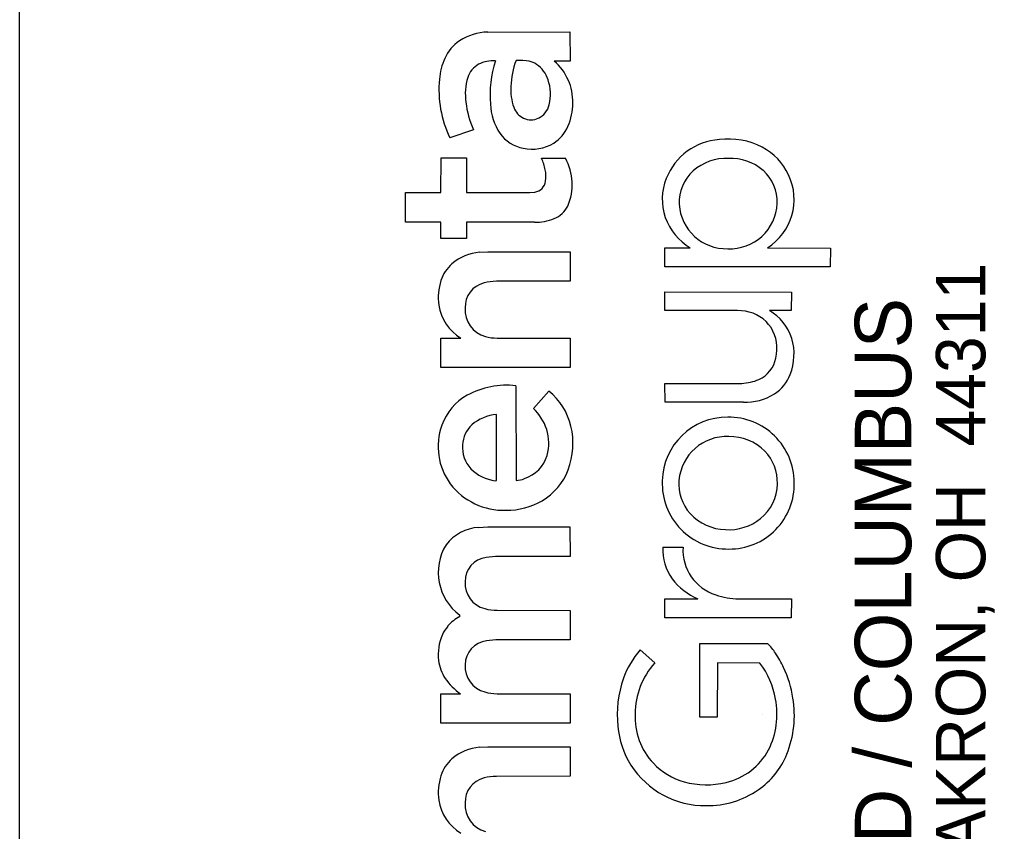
# Model space of a CAD drawing. Extents: x 0 to 54.8, y 0 to 22.
# Drawn here: x 32 to 32.984, y 3.382 to 4.202 of the extents above; entities that cross this region are included whole.
import ezdxf

# ---------------------------------------------------------------- set-up
doc = ezdxf.new("R2010")
doc.units = 0
for name, color, linetype in [('GM_X_Adjacent_County', 7, 'Continuous'), ('GM_X_Minor_Lake', 7, 'Continuous'), ('GM_X_Township', 7, 'Continuous')]:
    doc.layers.add(name, color=color, linetype=linetype)

msp = doc.modelspace()

# ---------------------------------------------------------------- linework, layer by layer
at = {"layer": 'GM_X_Adjacent_County'}
msp.add_line((32.75, 3.5), (32.75, 3.5), dxfattribs=at)
at = {"layer": 'GM_X_Minor_Lake'}
for p, q in [((32.47265, 4.18899), (32.55553, 4.18918)), ((32.55553, 4.18918), (32.55571, 4.15956)), ((32.55571, 4.15956), (32.53971, 4.15956)), ((32.45818, 4.09045), (32.43431, 4.08233)), ((32.42542, 4.02705), (32.42548, 4.06209)), ((32.42548, 4.06209), (32.45108, 4.06209)), ((32.45108, 4.06209), (32.45117, 4.02705)), ((32.52695, 4.06159), (32.5511, 4.06159)), ((32.38964, 4.02701), (32.42542, 4.02705)), ((32.38964, 3.99719), (32.38964, 4.02701)), ((32.45117, 4.02705), (32.51498, 4.02705)), ((32.51498, 4.02705), (32.52005, 4.02749)), ((32.42542, 3.99717), (32.38964, 3.99719)), ((32.42542, 3.98067), (32.42542, 3.99717)), ((32.51969, 3.99718), (32.45108, 3.99715)), ((32.45108, 3.99715), (32.45108, 3.98066)), ((32.45108, 3.98066), (32.42542, 3.98067)), ((32.46439, 3.96686), (32.47289, 3.96732)), ((32.47289, 3.96732), (32.55571, 3.96732)), ((32.55571, 3.96732), (32.55571, 3.93753)), ((32.65152, 3.97113), (32.67709, 3.97115)), ((32.65152, 3.95215), (32.65152, 3.97113)), ((32.75491, 3.97132), (32.81858, 3.97108)), ((32.81858, 3.97108), (32.81843, 3.95215)), ((32.81843, 3.95215), (32.65152, 3.95215)), ((32.55571, 3.93753), (32.4814, 3.93746)), ((32.65152, 3.90801), (32.65153, 3.92672)), ((32.65153, 3.92672), (32.7791, 3.92664)), ((32.7791, 3.92664), (32.77908, 3.90796)), ((32.7249, 3.90796), (32.65152, 3.90801)), ((32.7328, 3.90727), (32.7249, 3.90796)), ((32.77908, 3.90796), (32.75689, 3.90796)), ((32.42542, 3.88016), (32.44552, 3.88021)), ((32.42542, 3.85035), (32.42542, 3.88016)), ((32.48222, 3.88021), (32.55569, 3.88021)), ((32.55569, 3.88021), (32.55571, 3.85045)), ((32.55571, 3.85045), (32.42542, 3.85035)), ((32.50108, 3.83209), (32.50118, 3.73657)), ((32.65154, 3.83443), (32.72905, 3.8345)), ((32.65165, 3.81543), (32.65154, 3.83443)), ((32.51882, 3.80927), (32.53422, 3.82662)), ((32.73073, 3.81543), (32.65165, 3.81543)), ((32.48144, 3.73644), (32.48144, 3.80296)), ((32.48016, 3.73628), (32.48144, 3.73644)), ((32.46329, 3.68915), (32.47259, 3.68968)), ((32.47259, 3.68968), (32.55557, 3.68968)), ((32.55557, 3.68968), (32.55571, 3.65982)), ((32.64932, 3.66907), (32.66978, 3.66907)), ((32.48058, 3.65981), (32.47102, 3.65881)), ((32.55571, 3.65982), (32.48058, 3.65981)), ((32.65152, 3.61699), (32.68476, 3.617)), ((32.65152, 3.598), (32.65152, 3.61699)), ((32.72605, 3.61703), (32.7791, 3.61696)), ((32.7791, 3.61696), (32.77903, 3.598)), ((32.48218, 3.60553), (32.55571, 3.60548)), ((32.55571, 3.60548), (32.55571, 3.57568)), ((32.44443, 3.59922), (32.44455, 3.60072)), ((32.77903, 3.598), (32.65152, 3.598)), ((32.4809, 3.57567), (32.47143, 3.57474)), ((32.55571, 3.57568), (32.4809, 3.57567)), ((32.62636, 3.56548), (32.64114, 3.55241)), ((32.6868, 3.57185), (32.75516, 3.57192)), ((32.6868, 3.49778), (32.6868, 3.57185)), ((32.70448, 3.55241), (32.70432, 3.49775)), ((32.74737, 3.55227), (32.70448, 3.55241)), ((32.42542, 3.49152), (32.42545, 3.52138)), ((32.42545, 3.52138), (32.44515, 3.52138)), ((32.48206, 3.52138), (32.55571, 3.52136)), ((32.55571, 3.52136), (32.55571, 3.49156)), ((32.70432, 3.49775), (32.6868, 3.49778)), ((32.55571, 3.49156), (32.42542, 3.49152)), ((32.46439, 3.46736), (32.47289, 3.46783)), ((32.47289, 3.46783), (32.55571, 3.46783)), ((32.55571, 3.46783), (32.55571, 3.43804)), ((32.55571, 3.43804), (32.4814, 3.43796))]:
    msp.add_line(p, q, dxfattribs=at)
for points in [[(32.47265, 4.18899), (32.55553, 4.18918), (32.55571, 4.15956)], [(32.55571, 4.15956), (32.53971, 4.15956)], [(32.45818, 4.09045), (32.43431, 4.08233)], [(32.51969, 3.99718), (32.45108, 3.99715), (32.45108, 3.98066), (32.42542, 3.98067), (32.42542, 3.99717), (32.38964, 3.99719), (32.38964, 4.02701), (32.42542, 4.02705), (32.42548, 4.06209), (32.45108, 4.06209), (32.45117, 4.02705), (32.51498, 4.02705), (32.52005, 4.02749)], [(32.52695, 4.06159), (32.5511, 4.06159)], [(32.46439, 3.96686), (32.47289, 3.96732), (32.55571, 3.96732), (32.55571, 3.93753), (32.4814, 3.93746)], [(32.75491, 3.97132), (32.81858, 3.97108), (32.81843, 3.95215), (32.65152, 3.95215)], [(32.65152, 3.95215), (32.65152, 3.97113), (32.67709, 3.97115)], [(32.7328, 3.90727), (32.7249, 3.90796), (32.65152, 3.90801), (32.65153, 3.92672), (32.7791, 3.92664), (32.77908, 3.90796), (32.75689, 3.90796)], [(32.42542, 3.85035), (32.42542, 3.88016), (32.44552, 3.88021)], [(32.48222, 3.88021), (32.55569, 3.88021), (32.55571, 3.85045), (32.42542, 3.85035)], [(32.50108, 3.83209), (32.50118, 3.73657)], [(32.73073, 3.81543), (32.65165, 3.81543), (32.65154, 3.83443), (32.72905, 3.8345)], [(32.51882, 3.80927), (32.53422, 3.82662)], [(32.48016, 3.73628), (32.48144, 3.73644), (32.48144, 3.80296)], [(32.46329, 3.68915), (32.47259, 3.68968), (32.55557, 3.68968), (32.55571, 3.65982), (32.48058, 3.65981), (32.47102, 3.65881)], [(32.64932, 3.66907), (32.66978, 3.66907)], [(32.72605, 3.61703), (32.7791, 3.61696), (32.77903, 3.598), (32.65152, 3.598)], [(32.65152, 3.598), (32.65152, 3.61699), (32.68476, 3.617)], [(32.48218, 3.60553), (32.55571, 3.60548), (32.55571, 3.57568), (32.4809, 3.57567), (32.47143, 3.57474)], [(32.44443, 3.59922), (32.44455, 3.60072)], [(32.62636, 3.56548), (32.64114, 3.55241)], [(32.74737, 3.55227), (32.70448, 3.55241), (32.70432, 3.49775), (32.6868, 3.49778), (32.6868, 3.57185), (32.75516, 3.57192)], [(32.42542, 3.49152), (32.42545, 3.52138), (32.44515, 3.52138)], [(32.48206, 3.52138), (32.55571, 3.52136), (32.55571, 3.49156), (32.42542, 3.49152)], [(32.46439, 3.46736), (32.47289, 3.46783), (32.55571, 3.46783), (32.55571, 3.43804), (32.4814, 3.43796)]]:
    msp.add_lwpolyline(points, dxfattribs=at)
for centre, radius, start, end in [((32.47452, 4.13256), 0.05646, 91.89422, 122.63175), ((32.47452, 4.13256), 0.05646, 91.89422, 122.63175), ((32.46847, 4.14467), 0.04302, 124.53704, 155.65938), ((32.46847, 4.14467), 0.04302, 124.53704, 155.65938), ((32.48824, 4.13612), 0.06457, 155.9764, 175.31491), ((32.48824, 4.13612), 0.06457, 155.9764, 175.31491), ((32.47525, 4.1356), 0.024, 119.42515, 161.66285), ((32.47525, 4.1356), 0.024, 119.42515, 161.66285), ((32.47786, 4.12778), 0.03213, 85.38017, 116.62224), ((32.47786, 4.12778), 0.03213, 85.38017, 116.62224), ((32.58787, 4.12508), 0.1129, 162.08213, 184.52847), ((32.58787, 4.12508), 0.1129, 162.08213, 184.52847), ((32.58013, 4.13131), 0.08411, 159.83657, 178.03621), ((32.58013, 4.13131), 0.08411, 159.83657, 178.03621), ((32.50509, 4.10743), 0.05302, 79.66963, 94.23216), ((32.50509, 4.10743), 0.05302, 79.66963, 94.23216), ((32.50892, 4.13643), 0.02384, 56.89129, 76.21489), ((32.50892, 4.13643), 0.02384, 56.89129, 76.21489), ((32.5052, 4.13184), 0.02973, 17.59837, 55.72819), ((32.5052, 4.13184), 0.02973, 17.59837, 55.72819), ((32.50551, 4.11914), 0.05295, 358.07459, 49.76196), ((32.50551, 4.11914), 0.05295, 358.07459, 49.76196), ((32.53639, 4.13078), 0.113, 174.61011, 205.38987), ((32.53639, 4.13078), 0.113, 174.61011, 205.38987), ((32.50758, 4.12645), 0.05758, 163.13694, 188.16749), ((32.50758, 4.12645), 0.05758, 163.13694, 188.16749), ((32.54655, 4.1303), 0.05063, 175.59026, 199.88569), ((32.54655, 4.1303), 0.05063, 175.59026, 199.88569), ((32.4916, 4.1264), 0.04435, 345.94084, 18.99188), ((32.4916, 4.1264), 0.04435, 345.94084, 18.99188), ((32.54725, 4.12973), 0.09735, 186.75982, 203.79807), ((32.54725, 4.12973), 0.09735, 186.75982, 203.79807), ((32.53279, 4.11874), 0.05752, 182.56764, 213.71437), ((32.53279, 4.11874), 0.05752, 182.56764, 213.71437), ((32.51521, 4.11994), 0.01989, 295.28829, 347.46387), ((32.51521, 4.11994), 0.01989, 295.28829, 347.46387), ((32.50187, 4.11678), 0.05657, 336.01604, 0.59505), ((32.50187, 4.11678), 0.05657, 336.01604, 0.59505), ((32.51642, 4.11886), 0.01841, 198.28436, 293.30806), ((32.51642, 4.11886), 0.01841, 198.28436, 293.30806), ((32.51487, 4.10782), 0.03656, 215.06685, 259.81327), ((32.51487, 4.10782), 0.03656, 215.06685, 259.81327), ((32.51752, 4.10969), 0.03938, 303.44357, 336.18), ((32.51752, 4.10969), 0.03938, 303.44357, 336.18), ((32.51753, 4.1131), 0.04227, 257.52557, 300.88195), ((32.51753, 4.1131), 0.04227, 257.52557, 300.88195), ((32.71081, 4.01825), 0.06243, 93.98662, 158.31194), ((32.71081, 4.01825), 0.06243, 93.98662, 158.31194), ((32.71557, 4.0065), 0.07459, 62.68889, 97.01346), ((32.71557, 4.0065), 0.07459, 62.68889, 97.01346), ((32.72123, 4.01914), 0.06076, 25.06574, 61.96022), ((32.72123, 4.01914), 0.06076, 25.06574, 61.96022), ((32.48625, 4.04199), 0.04518, 10.15449, 25.72303), ((32.48625, 4.04199), 0.04518, 10.15449, 25.72303), ((32.50302, 4.03506), 0.05491, 336.58903, 28.89913), ((32.50302, 4.03506), 0.05491, 336.58903, 28.89913), ((32.71379, 4.01017), 0.05134, 87.89653, 131.18123), ((32.71379, 4.01017), 0.05134, 87.89653, 131.18123), ((32.7175, 4.01023), 0.05127, 49.90886, 92.03625), ((32.7175, 4.01023), 0.05127, 49.90886, 92.03625), ((32.49573, 4.04365), 0.03556, 351.91398, 10.20594), ((32.49573, 4.04365), 0.03556, 351.91398, 10.20594), ((32.7092, 4.01674), 0.04338, 132.32887, 182.09489), ((32.7092, 4.01674), 0.04338, 132.32887, 182.09489), ((32.72154, 4.01733), 0.04327, 358.04871, 47.94467), ((32.72154, 4.01733), 0.04327, 358.04871, 47.94467), ((32.7245, 4.02004), 0.05743, 301.97764, 25.64176), ((32.7245, 4.02004), 0.05743, 301.97764, 25.64176), ((32.51837, 4.04001), 0.01263, 277.61423, 353.79181), ((32.51837, 4.04001), 0.01263, 277.61423, 353.79181), ((32.70695, 4.02016), 0.05815, 158.65601, 198.17101), ((32.70695, 4.02016), 0.05815, 158.65601, 198.17101), ((32.71717, 4.01801), 0.04766, 267.31494, 357.4019), ((32.71717, 4.01801), 0.04766, 267.31494, 357.4019), ((32.52913, 4.02612), 0.02749, 292.68889, 332.05977), ((32.52913, 4.02612), 0.02749, 292.68889, 332.05977), ((32.71352, 4.01815), 0.04776, 183.59741, 271.7045), ((32.71352, 4.01815), 0.04776, 183.59741, 271.7045), ((32.52088, 4.04856), 0.05139, 268.67266, 291.52354), ((32.52088, 4.04856), 0.05139, 268.67266, 291.52354), ((32.7103, 4.02433), 0.0627, 200.83985, 238.01619), ((32.7103, 4.02433), 0.0627, 200.83985, 238.01619), ((32.46871, 3.91716), 0.04988, 94.97056, 130.22484), ((32.46871, 3.91716), 0.04988, 94.97056, 130.22484), ((32.46348, 3.92551), 0.04016, 132.22383, 161.68229), ((32.46348, 3.92551), 0.04016, 132.22383, 161.68229), ((32.47872, 3.92108), 0.05602, 162.27398, 187.79173), ((32.47872, 3.92108), 0.05602, 162.27398, 187.79173), ((32.48108, 3.89145), 0.04601, 89.60515, 105.33026), ((32.48108, 3.89145), 0.04601, 89.60515, 105.33026), ((32.47482, 3.91155), 0.02498, 103.68683, 182.21395), ((32.47482, 3.91155), 0.02498, 103.68683, 182.21395), ((32.47027, 3.9209), 0.04763, 188.96462, 238.69865), ((32.47027, 3.9209), 0.04763, 188.96462, 238.69865), ((32.47735, 3.90846), 0.02757, 175.58441, 255.13816), ((32.47735, 3.90846), 0.02757, 175.58441, 255.13816), ((32.72711, 3.86998), 0.03772, 33.50082, 81.32954), ((32.72711, 3.86998), 0.03772, 33.50082, 81.32954), ((32.73239, 3.86485), 0.04959, 17.62209, 60.38974), ((32.73239, 3.86485), 0.04959, 17.62209, 60.38974), ((32.72414, 3.8695), 0.04048, 346.56179, 31.75389), ((32.72414, 3.8695), 0.04048, 346.56179, 31.75389), ((32.48183, 3.92235), 0.04215, 254.08913, 270.52838), ((32.48183, 3.92235), 0.04215, 254.08913, 270.52838), ((32.72343, 3.86415), 0.05838, 339.16197, 15.61485), ((32.72343, 3.86415), 0.05838, 339.16197, 15.61485), ((32.73371, 3.86616), 0.03042, 294.63214, 348.48625), ((32.73371, 3.86616), 0.03042, 294.63214, 348.48625), ((32.72747, 3.88081), 0.04633, 271.95199, 294.08943), ((32.72747, 3.88081), 0.04633, 271.95199, 294.08943), ((32.739, 3.85901), 0.04201, 303.10391, 338.15613), ((32.739, 3.85901), 0.04201, 303.10391, 338.15613), ((32.49176, 3.74874), 0.08387, 83.62118, 118.28448), ((32.49176, 3.74874), 0.08387, 83.62118, 118.28448), ((32.47894, 3.77368), 0.05583, 118.82935, 160.62242), ((32.47894, 3.77368), 0.05583, 118.82935, 160.62242), ((32.49399, 3.7763), 0.06443, 13.53275, 51.36266), ((32.49399, 3.7763), 0.06443, 13.53275, 51.36266), ((32.7321, 3.87256), 0.05715, 268.62699, 301.47779), ((32.7321, 3.87256), 0.05715, 268.62699, 301.47779), ((32.48033, 3.77018), 0.05485, 19.0387, 45.44322), ((32.48033, 3.77018), 0.05485, 19.0387, 45.44322), ((32.4844, 3.76071), 0.04236, 94.01311, 130.88062), ((32.4844, 3.76071), 0.04236, 94.01311, 130.88062), ((32.71435, 3.73484), 0.06552, 89.48213, 178.77752), ((32.71435, 3.73484), 0.06552, 89.48213, 178.77752), ((32.71582, 3.73414), 0.06623, 0.42265, 90.7613), ((32.71582, 3.73414), 0.06623, 0.42265, 90.7613), ((32.48697, 3.77074), 0.06438, 160.52138, 215.78155), ((32.48697, 3.77074), 0.06438, 160.52138, 215.78155), ((32.47703, 3.7709), 0.02985, 132.98553, 177.1802), ((32.47703, 3.7709), 0.02985, 132.98553, 177.1802), ((32.48289, 3.77384), 0.0758, 339.35431, 13.37708), ((32.48289, 3.77384), 0.0758, 339.35431, 13.37708), ((32.48724, 3.77433), 0.04701, 344.60723, 17.00675), ((32.48724, 3.77433), 0.04701, 344.60723, 17.00675), ((32.71397, 3.73244), 0.04846, 87.68827, 175.01696), ((32.71397, 3.73244), 0.04846, 87.68827, 175.01696), ((32.71659, 3.73036), 0.05052, 44.91202, 90.75914), ((32.71659, 3.73036), 0.05052, 44.91202, 90.75914), ((32.47824, 3.76966), 0.03114, 175.00138, 223.2876), ((32.47824, 3.76966), 0.03114, 175.00138, 223.2876), ((32.49895, 3.77177), 0.03504, 288.01084, 343.55364), ((32.49895, 3.77177), 0.03504, 288.01084, 343.55364), ((32.71955, 3.73452), 0.04549, 358.32279, 43.83486), ((32.71955, 3.73452), 0.04549, 358.32279, 43.83486), ((32.48546, 3.77826), 0.04232, 225.06454, 262.79701), ((32.48546, 3.77826), 0.04232, 225.06454, 262.79701), ((32.49548, 3.76982), 0.0626, 300.94393, 338.73223), ((32.49548, 3.76982), 0.0626, 300.94393, 338.73223), ((32.48908, 3.77516), 0.06872, 217.74341, 271.65606), ((32.48908, 3.77516), 0.06872, 217.74341, 271.65606), ((32.50129, 3.75678), 0.02021, 269.70042, 294.87295), ((32.50129, 3.75678), 0.02021, 269.70042, 294.87295), ((32.71483, 3.7334), 0.06606, 177.53728, 270.94524), ((32.71483, 3.7334), 0.06606, 177.53728, 270.94524), ((32.71085, 3.73311), 0.0453, 175.51467, 221.42047), ((32.71085, 3.73311), 0.0453, 175.51467, 221.42047), ((32.71671, 3.73271), 0.06536, 269.30834, 1.67905), ((32.71671, 3.73271), 0.06536, 269.30834, 1.67905), ((32.71931, 3.73374), 0.04572, 308.90382, 359.30947), ((32.71931, 3.73374), 0.04572, 308.90382, 359.30947), ((32.49204, 3.77702), 0.07055, 269.20529, 300.33566), ((32.49204, 3.77702), 0.07055, 269.20529, 300.33566), ((32.71399, 3.73734), 0.05046, 222.66255, 268.37331), ((32.71399, 3.73734), 0.05046, 222.66255, 268.37331), ((32.71567, 3.73859), 0.05178, 266.55312, 308.67253), ((32.71567, 3.73859), 0.05178, 266.55312, 308.67253), ((32.46638, 3.64404), 0.04521, 93.91118, 142.30723), ((32.46638, 3.64404), 0.04521, 93.91118, 142.30723), ((32.47585, 3.64373), 0.05319, 148.28793, 233.9556), ((32.47585, 3.64373), 0.05319, 148.28793, 233.9556), ((32.69878, 3.66662), 0.04952, 177.16211, 216.28024), ((32.69878, 3.66662), 0.04952, 177.16211, 216.28024), ((32.71735, 3.66638), 0.04764, 176.76988, 252.15044), ((32.71735, 3.66638), 0.04764, 176.76988, 252.15044), ((32.47384, 3.63499), 0.02399, 96.75763, 181.6251), ((32.47384, 3.63499), 0.02399, 96.75763, 181.6251), ((32.47577, 3.63241), 0.02597, 175.81573, 256.16716), ((32.47577, 3.63241), 0.02597, 175.81573, 256.16716), ((32.70975, 3.67555), 0.06366, 216.91526, 246.88619), ((32.70975, 3.67555), 0.06366, 216.91526, 246.88619), ((32.7269, 3.69175), 0.07473, 251.13884, 269.34694), ((32.7269, 3.69175), 0.07473, 251.13884, 269.34694), ((32.4817, 3.65053), 0.04501, 254.34629, 270.61033), ((32.4817, 3.65053), 0.04501, 254.34629, 270.61033), ((32.4638, 3.56267), 0.04137, 117.91625, 139.24296), ((32.4638, 3.56267), 0.04137, 117.91625, 139.24296), ((32.46194, 3.56452), 0.03875, 139.52447, 154.84698), ((32.46194, 3.56452), 0.03875, 139.52447, 154.84698), ((32.47144, 3.5612), 0.04877, 156.06382, 187.3493), ((32.47144, 3.5612), 0.04877, 156.06382, 187.3493), ((32.47421, 3.55056), 0.02434, 96.5532, 179.94902), ((32.47421, 3.55056), 0.02434, 96.5532, 179.94902), ((32.70163, 3.50187), 0.09855, 139.79476, 159.13696), ((32.70163, 3.50187), 0.09855, 139.79476, 159.13696), ((32.72498, 3.53937), 0.04438, 30.98913, 47.16099), ((32.72498, 3.53937), 0.04438, 30.98913, 47.16099), ((32.46461, 3.55974), 0.04181, 186.5579, 213.38846), ((32.46461, 3.55974), 0.04181, 186.5579, 213.38846), ((32.67091, 3.50018), 0.11106, 25.30315, 33.96179), ((32.67091, 3.50018), 0.11106, 25.30315, 33.96179), ((32.47608, 3.54863), 0.02628, 175.722, 255.78627), ((32.47608, 3.54863), 0.02628, 175.722, 255.78627), ((32.69899, 3.50079), 0.07753, 138.25804, 179.70064), ((32.69899, 3.50079), 0.07753, 138.25804, 179.70064), ((32.67889, 3.50099), 0.08556, 10.07509, 36.83189), ((32.67889, 3.50099), 0.08556, 10.07509, 36.83189), ((32.6704, 3.49987), 0.11166, 8.80339, 25.33484), ((32.6704, 3.49987), 0.11166, 8.80339, 25.33484), ((32.47886, 3.57078), 0.0598, 214.70433, 235.68724), ((32.47886, 3.57078), 0.0598, 214.70433, 235.68724), ((32.7187, 3.49968), 0.11536, 161.14379, 185.62812), ((32.7187, 3.49968), 0.11536, 161.14379, 185.62812), ((32.48195, 3.56518), 0.0438, 253.66719, 270.14979), ((32.48195, 3.56518), 0.0438, 253.66719, 270.14979), ((32.68425, 3.50057), 0.08036, 333.46689, 11.03668), ((32.68425, 3.50057), 0.08036, 333.46689, 11.03668), ((32.67564, 3.49977), 0.10649, 338.28866, 9.28548), ((32.67564, 3.49977), 0.10649, 338.28866, 9.28548), ((32.68811, 3.49732), 0.06676, 176.66577, 223.6912), ((32.68811, 3.49732), 0.06676, 176.66577, 223.6912), ((32.69336, 3.49699), 0.08987, 185.50773, 212.01294), ((32.69336, 3.49699), 0.08987, 185.50773, 212.01294), ((32.46871, 3.41767), 0.04988, 94.97056, 130.22484), ((32.46871, 3.41767), 0.04988, 94.97056, 130.22484), ((32.69868, 3.49547), 0.0652, 282.88151, 331.81475), ((32.69868, 3.49547), 0.0652, 282.88151, 331.81475), ((32.46348, 3.42602), 0.04016, 132.22383, 161.68229), ((32.46348, 3.42602), 0.04016, 132.22383, 161.68229), ((32.69835, 3.49168), 0.08241, 305.03061, 337.67573), ((32.69835, 3.49168), 0.08241, 305.03061, 337.67573), ((32.69211, 3.49748), 0.08908, 212.70222, 270.71399), ((32.69211, 3.49748), 0.08908, 212.70222, 270.71399), ((32.69045, 3.50011), 0.07039, 224.02147, 253.88), ((32.69045, 3.50011), 0.07039, 224.02147, 253.88), ((32.47872, 3.42158), 0.05602, 162.27398, 187.79173), ((32.47872, 3.42158), 0.05602, 162.27398, 187.79173), ((32.47482, 3.41206), 0.02498, 103.68683, 182.21395), ((32.47482, 3.41206), 0.02498, 103.68683, 182.21395), ((32.48108, 3.39196), 0.04601, 89.60515, 105.33026), ((32.48108, 3.39196), 0.04601, 89.60515, 105.33026), ((32.69318, 3.51254), 0.08309, 254.45353, 283.9512), ((32.69318, 3.51254), 0.08309, 254.45353, 283.9512), ((32.69429, 3.49979), 0.09138, 269.3273, 304.19632), ((32.69429, 3.49979), 0.09138, 269.3273, 304.19632), ((32.47027, 3.42141), 0.04763, 188.96462, 238.69865), ((32.47027, 3.42141), 0.04763, 188.96462, 238.69865), ((32.47735, 3.40897), 0.02757, 175.58441, 255.13816), ((32.47735, 3.40897), 0.02757, 175.58441, 255.13816)]:
    msp.add_arc(centre, radius, start, end, dxfattribs=at)
at = {"layer": 'GM_X_Township'}
msp.add_line((32, 0.5), (32, 21.5), dxfattribs=at)

# ---------------------------------------------------------------- texts
at = {"layer": 'GM_X_Minor_Lake'}
for s, height, p in [('450 GRANT ST., AKRON, OH  44311', 0.0498462, (32.97489, 2.83738)), ('AKRON / CLEVELAND / COLUMBUS', 0.056969, (32.90012, 2.638))]:
    msp.add_text(s, height=height, rotation=90, dxfattribs=at).set_placement(p)

doc.saveas('drawing.dxf')
